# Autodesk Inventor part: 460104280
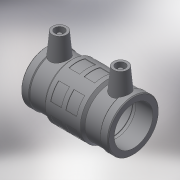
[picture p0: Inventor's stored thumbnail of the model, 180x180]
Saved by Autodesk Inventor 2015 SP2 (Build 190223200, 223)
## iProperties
Created: 2017-06
Part Number: 460104280
Material: Generic
Description: PLASSON LIGHTFIT COUPLER 280
Document SubType Name: Modeling
Designer: KIM
Mass: 89.5427 g
Surface Area: 304.58 cm^2
Volume: 89.5427 cm^3
Density: 1 g/cm^3
Appearance: Default
Author: KIM
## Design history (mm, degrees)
derived "460104.ipt"
feature "Solid1::460104.ipt"
tag "TaggingFeature1"
body "Solid1"
other parameters: "d13" = 275, "d14" = 17.6296, "d15" = 135, "d16" = 135, "d17" = 277.2, "d19" = 3.52592, "d20" = 168 deg, "d22" = 312.08, "d23" = 332, "d24" = 302.7176, "d25" = 135 deg, "d27" = 135 deg, "d29" = 166, "d35" = 15, "d39" = 5 deg, "d44" = 4, "d46" = 14, "d47" = 0, "d52" = 325.36, "d53" = 13.75, "d54" = 13.75, "d55" = 13.75, "d56" = 35 deg, "d58" = 360 deg, "d60" = 27, "d61" = 135 deg, "d62" = 123.75, "d63" = 3, "d64" = 0, "L_" = 275, "L_1" = 135, "D_" = 332, "A_" = 166, "d_2" = 12
